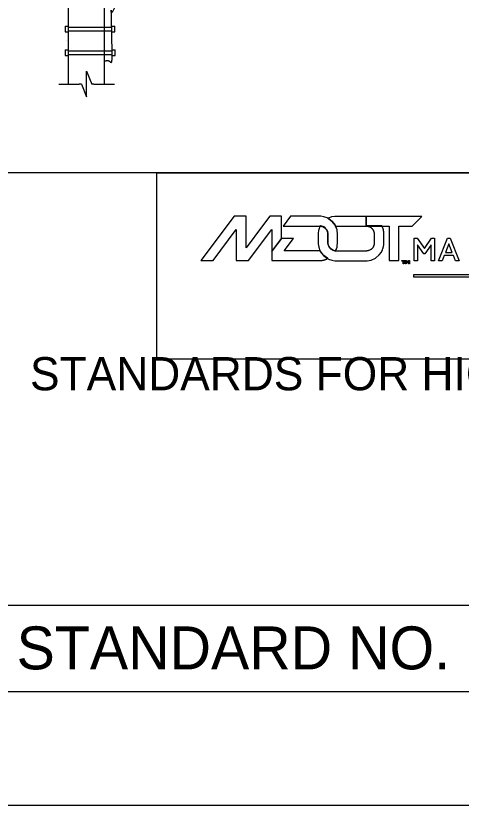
# Model space of a CAD drawing. Extents: x 12.2 to 54.5, y -7.8 to 16.1.
# Drawn here: x 50.1 to 51.346, y -7.78 to -5.573 of the extents above; entities that cross this region are included whole.
import ezdxf

# ---------------------------------------------------------------- set-up
doc = ezdxf.new("R2010")
doc.units = 0
for name, color, linetype in [('BORD-LINE', 7, 'Continuous'), ('DETL-DIMS', 7, 'Continuous'), ('DETL-LINE', 7, 'Continuous'), ('MSHA-LOGO', 7, 'Continuous'), ('TTLB-TEXT', 7, 'Continuous'), ('USER-BORD', 7, 'Continuous'), ('USER-LINE', 7, 'Continuous')]:
    doc.layers.add(name, color=color, linetype=linetype)

msp = doc.modelspace()

# ---------------------------------------------------------------- linework, layer by layer
at = {"layer": 'BORD-LINE'}
for p, q in [((54.2173, -6.0121), (49.7444, -6.0121)), ((49.7444, -7.2211), (54.2173, -7.2211))]:
    msp.add_line(p, q, dxfattribs=at)
msp.add_lwpolyline([(46.8431, 2.8902), (54.2173, 2.8902), (54.2173, -7.4629), (46.8431, -7.4629)], close=True, dxfattribs=at)
at = {"layer": 'DETL-DIMS'}
msp.add_line((50.2423, -5.6436), (50.2423, -5.6436), dxfattribs=at)
at = {"layer": 'DETL-LINE'}
for p, q in [((50.248, -5.7641), (50.2481, -5.2986)), ((50.3485, -5.7641), (50.3485, -5.332)), ((50.2389, -5.6025), (50.2389, -5.6186)), ((50.2389, -5.6025), (50.248, -5.6025)), ((50.248, -5.6186), (50.248, -5.6025)), ((50.3679, -5.6025), (50.3679, -5.6186)), ((50.3679, -5.6025), (50.377, -5.6025)), ((50.377, -5.6186), (50.377, -5.6025)), ((50.2389, -5.6186), (50.248, -5.6186)), ((50.248, -5.6056), (50.3679, -5.6056)), ((50.248, -5.6156), (50.3679, -5.6156)), ((50.3679, -5.6186), (50.377, -5.6186)), ((50.2389, -5.6687), (50.2389, -5.6848)), ((50.2389, -5.6687), (50.248, -5.6687)), ((50.248, -5.6848), (50.248, -5.6687)), ((50.3688, -5.6687), (50.3688, -5.6848)), ((50.3688, -5.6687), (50.378, -5.6687)), ((50.378, -5.6848), (50.378, -5.6687)), ((50.2389, -5.6848), (50.248, -5.6848)), ((50.248, -5.6717), (50.3688, -5.6717)), ((50.248, -5.6817), (50.3686, -5.6817)), ((50.3688, -5.6848), (50.378, -5.6848)), ((50.3516, -5.7001), (50.3485, -5.7001)), ((50.2982, -5.8), (50.2982, -5.7282)), ((50.2982, -5.7282), (50.3127, -5.7641)), ((50.2204, -5.7641), (50.2776, -5.7641)), ((50.2838, -5.7641), (50.2776, -5.7641)), ((50.2838, -5.7641), (50.2982, -5.8)), ((50.3189, -5.7641), (50.3127, -5.7641)), ((50.3189, -5.7641), (50.3761, -5.7641))]:
    msp.add_line(p, q, dxfattribs=at)
for points in [[(50.3897, -5.5161), (50.3679, -5.578), (50.3663, -5.5424), (50.3687, -5.6641)], [(50.3687, -5.6641), (50.3701, -5.7102), (50.3611, -5.6977), (50.3516, -5.7001)]]:
    msp.add_open_spline(points, degree=2, dxfattribs=at)
at = {"layer": 'MSHA-LOGO'}
for points in [[(50.8164, -6.2321), (50.8436, -6.196), (50.8436, -6.1333), (50.8106, -6.1333), (50.7901, -6.1607), (50.7443, -6.2218), (50.7443, -6.1333), (50.7113, -6.1333), (50.6181, -6.2576), (50.6521, -6.2576), (50.7172, -6.1708), (50.7172, -6.2576), (50.7513, -6.2576), (50.8164, -6.1708)], [(50.9515, -6.1612), (50.9524, -6.1612), (50.96, -6.1632), (50.9606, -6.1636), (50.9615, -6.164), (50.9653, -6.1667), (50.9685, -6.1701), (50.9691, -6.1708), (50.9697, -6.1717), (50.9719, -6.1763), (50.9731, -6.1815), (50.9732, -6.1825), (50.9732, -6.1825), (50.9732, -6.1827), (50.9732, -6.1827), (50.9732, -6.183), (50.9732, -6.1835), (50.9732, -6.1837), (50.9732, -6.2073), (50.9732, -6.2076), (50.9732, -6.2082), (50.9732, -6.2084), (50.9732, -6.2084), (50.9732, -6.2085), (50.9732, -6.2085), (50.9732, -6.209), (50.973, -6.2102), (50.973, -6.2106), (50.9733, -6.2125), (50.9755, -6.2182), (50.9802, -6.2244), (50.9869, -6.2289), (50.9931, -6.2308), (50.9944, -6.2309), (50.9946, -6.2305), (50.9948, -6.2302), (50.9948, -6.2302), (50.995, -6.2298), (50.997, -6.2254), (50.9972, -6.2249), (50.9974, -6.2244), (50.9988, -6.2197), (50.9989, -6.2192), (50.999, -6.219), (50.9996, -6.2165), (50.9996, -6.2163), (50.9997, -6.2155), (51.0005, -6.2093), (51.0005, -6.2072), (51.0005, -6.1841), (51.0005, -6.1818), (50.9997, -6.1757), (50.9996, -6.175), (50.9996, -6.1747), (50.999, -6.1723), (50.9989, -6.172), (50.9988, -6.1715), (50.9974, -6.1668), (50.9972, -6.1663), (50.997, -6.1659), (50.995, -6.1614), (50.9948, -6.161), (50.9936, -6.1587), (50.9857, -6.1485), (50.9755, -6.1405), (50.9732, -6.1393), (50.9715, -6.1384), (50.9623, -6.1352), (50.9533, -6.1338), (50.9503, -6.1338), (50.8685, -6.1338), (50.848, -6.161), (50.9503, -6.161), (50.9504, -6.161), (50.9513, -6.1612)], [(50.995, -6.1613), (50.9954, -6.1613), (50.9957, -6.1613), (51.0796, -6.1613), (51.0798, -6.1613), (51.08, -6.1613), (51.0801, -6.1613), (51.0803, -6.161), (51.0803, -6.134), (51.0803, -6.134), (51.0798, -6.134), (51.0796, -6.134), (50.9957, -6.134), (50.9927, -6.134), (50.9837, -6.1354), (50.9746, -6.1386), (50.9732, -6.1393), (50.9755, -6.1405), (50.9857, -6.1485), (50.9936, -6.1587), (50.9948, -6.161)], [(51.0803, -6.134), (51.0803, -6.1612), (51.1447, -6.1612), (51.1447, -6.2576), (51.1717, -6.2576), (51.1717, -6.1612), (51.2093, -6.1612), (51.2362, -6.1341), (51.2362, -6.134)], [(50.9737, -6.2521), (50.9736, -6.2521), (50.9734, -6.252), (50.9734, -6.2519), (50.9722, -6.2513), (50.9619, -6.2437), (50.961, -6.2428), (50.9601, -6.2419), (50.9527, -6.2317), (50.9521, -6.2306), (50.9519, -6.2306), (50.9516, -6.2306), (50.9515, -6.2306), (50.9512, -6.2306), (50.9506, -6.2306), (50.9503, -6.2306), (50.8509, -6.2306), (50.8774, -6.1956), (50.8434, -6.1956), (50.8163, -6.2316), (50.8163, -6.2578), (50.9502, -6.2578), (50.9509, -6.2578), (50.953, -6.2577), (50.9533, -6.2576), (50.954, -6.2576), (50.9559, -6.2573), (50.9562, -6.2573), (50.9564, -6.2573), (50.9569, -6.2571), (50.957, -6.2571), (50.9572, -6.2571), (50.9587, -6.2568), (50.9589, -6.2568), (50.9592, -6.2568), (50.9598, -6.2566), (50.96, -6.2566), (50.9601, -6.2565), (50.9615, -6.2563), (50.9617, -6.2562), (50.9618, -6.2562), (50.9626, -6.2559), (50.9627, -6.2559), (50.9628, -6.2558), (50.9641, -6.2554), (50.9642, -6.2554), (50.9643, -6.2553), (50.9652, -6.2551), (50.9653, -6.255), (50.9654, -6.255), (50.9667, -6.2545), (50.9668, -6.2545), (50.9669, -6.2545), (50.9678, -6.2542), (50.9679, -6.2542), (50.968, -6.2541), (50.9694, -6.2535), (50.9696, -6.2535), (50.9697, -6.2534), (50.9703, -6.2532), (50.9704, -6.2531), (50.9706, -6.253), (50.9727, -6.2521), (50.9728, -6.2519), (50.973, -6.252), (50.9735, -6.2521)], [(51.2145, -6.1945), (51.2233, -6.1945), (51.2436, -6.2241), (51.2632, -6.1945), (51.2718, -6.1945), (51.2718, -6.258), (51.2619, -6.258), (51.2619, -6.2139), (51.2446, -6.2392), (51.242, -6.2392), (51.2243, -6.2139), (51.2243, -6.258), (51.2145, -6.258)], [(51.3081, -6.1945), (51.3156, -6.1945), (51.3405, -6.258), (51.33, -6.258), (51.3244, -6.2438), (51.2986, -6.2438), (51.293, -6.258), (51.2829, -6.258)], [(51.3025, -6.2346), (51.3212, -6.2346), (51.3117, -6.2106)], [(51.1803, -6.2576), (51.1892, -6.2576), (51.1892, -6.2592), (51.1857, -6.2592), (51.1857, -6.2666), (51.1839, -6.2666), (51.1839, -6.2592), (51.1803, -6.2592)], [(51.1904, -6.2576), (51.192, -6.2576), (51.1959, -6.262), (51.1995, -6.2576), (51.2011, -6.2576), (51.2011, -6.2666), (51.1991, -6.2666), (51.1991, -6.2601), (51.1956, -6.2643), (51.1922, -6.2601), (51.1922, -6.2666), (51.1904, -6.2666)], [(51.2136, -6.2962), (53.3302, -6.2962), (53.3302, -6.3041), (51.2136, -6.3041)]]:
    msp.add_lwpolyline(points, close=True, dxfattribs=at)
for points in [[(50.9732, -6.197), (50.9732, -6.1841), (50.9732, -6.1837), (50.9732, -6.183), (50.9732, -6.1827), (50.9732, -6.1822), (50.9734, -6.181), (50.9734, -6.1806), (50.9732, -6.1797), (50.9699, -6.1714), (50.9694, -6.1707), (50.9688, -6.1699), (50.9656, -6.1664), (50.9617, -6.1637), (50.9608, -6.1632), (50.9601, -6.1628), (50.9525, -6.1609), (50.9517, -6.1608), (50.9517, -6.1609), (50.9515, -6.1612), (50.9512, -6.1618), (50.9485, -6.1686), (50.9483, -6.1693), (50.9482, -6.1695), (50.9475, -6.1719), (50.9474, -6.1722), (50.9472, -6.1731), (50.9461, -6.1813), (50.9461, -6.1841), (50.9461, -6.197), (50.9461, -6.1984)], [(51.1299, -6.1841), (51.1299, -6.1833), (51.1298, -6.1814), (51.1298, -6.1812), (51.1298, -6.181), (51.1298, -6.1803), (51.1298, -6.1798), (51.1296, -6.1786), (51.1296, -6.1782), (51.1296, -6.1781), (51.1296, -6.1778), (51.1296, -6.1777), (51.1296, -6.1776), (51.1296, -6.1774), (51.1296, -6.1774), (51.1295, -6.1772), (51.1293, -6.1755), (51.1292, -6.1753), (51.1292, -6.1751), (51.1291, -6.1747), (51.1291, -6.1746), (51.129, -6.1744), (51.1286, -6.1725), (51.1286, -6.1724), (51.1286, -6.1722), (51.1286, -6.172), (51.1285, -6.1718), (51.1278, -6.1692), (51.1277, -6.1689), (51.1276, -6.1685), (51.126, -6.1642), (51.1258, -6.1638), (51.1257, -6.1635), (51.1247, -6.1614), (51.1246, -6.1612), (51.1246, -6.1611), (51.1244, -6.1608), (51.081, -6.1608), (51.0808, -6.1612), (51.0813, -6.1612), (51.0815, -6.1612), (51.0817, -6.1612), (51.0823, -6.1613), (51.0824, -6.1613), (51.0827, -6.1614), (51.0862, -6.1621), (51.0865, -6.1622), (51.0868, -6.1623), (51.0896, -6.1633), (51.0899, -6.1634), (51.0901, -6.1635), (51.0916, -6.1644), (51.0918, -6.1644), (51.0919, -6.1644), (51.092, -6.1644), (51.0921, -6.1645), (51.0936, -6.1654), (51.0937, -6.1655), (51.0939, -6.1656), (51.0939, -6.1657), (51.094, -6.1657), (51.0953, -6.1667), (51.0954, -6.1669), (51.0956, -6.167), (51.0957, -6.1671), (51.0967, -6.1681), (51.0968, -6.1682), (51.0969, -6.1684), (51.097, -6.1684), (51.0971, -6.1686), (51.0972, -6.1687), (51.098, -6.1695), (51.098, -6.1696), (51.0982, -6.1698), (51.0982, -6.1698), (51.0985, -6.1703), (51.0985, -6.1703), (51.0986, -6.1704), (51.0993, -6.1714), (51.0994, -6.1715), (51.0994, -6.1715), (51.0997, -6.1721), (51.0997, -6.1722), (51.0998, -6.1724), (51.0999, -6.1724), (51.0999, -6.1725), (51.1004, -6.1733), (51.1004, -6.1734), (51.1004, -6.1735), (51.1007, -6.1742), (51.1007, -6.1743), (51.1008, -6.1743), (51.1012, -6.1753), (51.1013, -6.1755), (51.1013, -6.1755), (51.1014, -6.1762), (51.1014, -6.1762), (51.1016, -6.1765), (51.1016, -6.1765), (51.1016, -6.1766), (51.102, -6.1773), (51.102, -6.1775), (51.102, -6.1776), (51.1022, -6.1787), (51.1023, -6.1787), (51.1023, -6.179), (51.1025, -6.1796), (51.1025, -6.1798), (51.1025, -6.1799), (51.1026, -6.1808), (51.1026, -6.1812), (51.1026, -6.1814), (51.1028, -6.1819), (51.1028, -6.182), (51.1028, -6.1826), (51.103, -6.1838), (51.103, -6.1842), (51.103, -6.2078), (51.103, -6.2084), (51.1028, -6.2099), (51.1028, -6.2101), (51.1028, -6.2103), (51.1027, -6.2109), (51.1026, -6.2109), (51.1026, -6.2113), (51.1025, -6.2121), (51.1025, -6.2123), (51.1025, -6.2126), (51.1023, -6.2132), (51.1023, -6.2134), (51.1022, -6.2134), (51.102, -6.2145), (51.102, -6.2146), (51.1019, -6.2146), (51.1016, -6.2155), (51.1016, -6.2156), (51.1016, -6.2157), (51.1015, -6.2159), (51.1014, -6.2159), (51.1013, -6.2164), (51.1013, -6.2166), (51.1012, -6.2167), (51.1008, -6.2177), (51.1007, -6.2178), (51.1007, -6.2179), (51.1004, -6.2186), (51.1004, -6.2187), (51.1004, -6.2188), (51.0999, -6.2196), (51.0999, -6.2197), (51.0998, -6.2199), (51.0997, -6.2199), (51.0997, -6.2199), (51.0994, -6.2205), (51.0994, -6.2206), (51.0993, -6.2207), (51.0986, -6.2217), (51.0985, -6.2218), (51.0985, -6.2218), (51.0982, -6.2223), (51.0982, -6.2223), (51.098, -6.2225), (51.0979, -6.2226), (51.0972, -6.2234), (51.0971, -6.2235), (51.097, -6.2237), (51.0968, -6.2239), (51.0968, -6.2239), (51.0967, -6.2239), (51.0957, -6.225), (51.0956, -6.2251), (51.0954, -6.2252), (51.0953, -6.2253), (51.094, -6.2263), (51.0939, -6.2264), (51.0937, -6.2266), (51.0937, -6.2266), (51.0936, -6.2267), (51.0922, -6.2276), (51.092, -6.2276), (51.0919, -6.2276), (51.0918, -6.2276), (51.0917, -6.2277), (51.0901, -6.2286), (51.0899, -6.2287), (51.0897, -6.2288), (51.0868, -6.2298), (51.0865, -6.2299), (51.0862, -6.23), (51.0827, -6.2307), (51.0824, -6.2307), (51.0822, -6.2307), (51.0816, -6.2309), (51.0815, -6.2309), (51.0812, -6.2309), (51.0805, -6.2309), (51.0803, -6.2309), (50.9964, -6.2309), (50.9961, -6.2309), (50.9954, -6.2309), (50.9952, -6.2309), (50.9931, -6.2308), (50.9869, -6.2289), (50.9802, -6.2242), (50.9755, -6.2175), (50.9736, -6.2115), (50.9735, -6.2094), (50.9735, -6.209), (50.9735, -6.2083), (50.9735, -6.208), (50.9735, -6.197), (50.9732, -6.197)], [(50.9461, -6.1984), (50.9461, -6.208), (50.9461, -6.211), (50.9475, -6.22), (50.9507, -6.2292), (50.9515, -6.2309), (50.9521, -6.2321), (50.9597, -6.2425), (50.9606, -6.2435), (50.9615, -6.2444), (50.972, -6.252), (50.9732, -6.2526), (50.9749, -6.2535), (50.9841, -6.2567), (50.993, -6.2581), (50.996, -6.2581), (51.08, -6.2581), (51.0835, -6.2581), (51.0939, -6.2561), (51.1063, -6.2506), (51.1167, -6.242), (51.1229, -6.2339), (51.1244, -6.2309), (51.1246, -6.2307), (51.1256, -6.2286), (51.1256, -6.2283), (51.1258, -6.2279), (51.1274, -6.2236), (51.1275, -6.2232), (51.1276, -6.2229), (51.1283, -6.2203), (51.1284, -6.2201), (51.1284, -6.2199), (51.1284, -6.2197), (51.1284, -6.2196), (51.1289, -6.2177), (51.1289, -6.2175), (51.1289, -6.2173), (51.1291, -6.2169), (51.1291, -6.2168), (51.1291, -6.2166), (51.1294, -6.2149), (51.1294, -6.2147), (51.1294, -6.2146), (51.1294, -6.2144), (51.1294, -6.2144), (51.1294, -6.2143), (51.1294, -6.214), (51.1294, -6.2139), (51.1294, -6.2134), (51.1296, -6.2122), (51.1296, -6.2118), (51.1296, -6.2111), (51.1296, -6.2109), (51.1296, -6.2102), (51.1298, -6.2086), (51.1298, -6.208), (51.1299, -6.1841)]]:
    msp.add_lwpolyline(points, dxfattribs=at)
at = {"layer": 'USER-BORD'}
msp.add_lwpolyline([(54.5342, 3.2202), (46.0342, 3.2202), (46.0342, -7.7798), (54.5342, -7.7798)], close=True, dxfattribs=at)
at = {"layer": 'USER-LINE'}
msp.add_lwpolyline([(53.4665, -6.5328), (50.4953, -6.5328), (50.4953, -6.0121), (53.4665, -6.0121)], close=True, dxfattribs=at)

# ---------------------------------------------------------------- texts
at = {"layer": 'TTLB-TEXT'}
for s, height, p in [('STANDARDS FOR HIGHWAYS AND INCIDENTAL STRUCTURES', 0.09269, (50.1402, -6.6201)), ('STANDARD NO.', 0.12, (50.1026, -7.4001))]:
    msp.add_text(s, height=height, rotation=360, dxfattribs=at).set_placement(p)

doc.saveas('drawing.dxf')
